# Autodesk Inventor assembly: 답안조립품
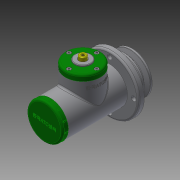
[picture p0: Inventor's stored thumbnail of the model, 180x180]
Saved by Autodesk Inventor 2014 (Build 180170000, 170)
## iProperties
Created: 2016-08
Part Number: 답안조립품
Document SubType Name: Assembly
Designer: USER
Author: USER
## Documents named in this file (25)
- C:\Users\USER\Desktop\460807V1008\답안조립품.iam
- C:\Users\USER\Desktop\460807V1008\본체.ipt
- C:\Users\USER\Desktop\460807V1008\V-벨트풀리.ipt
- C:\Users\USER\Desktop\460807V1008\너트 M10.ipt
- C:\Users\USER\Desktop\460807V1008\링크.ipt
- C:\Users\USER\Desktop\460807V1008\멈춤링 15 x 1.ipt
- C:\Users\USER\Desktop\460807V1008\멈춤링 35x1.6.ipt
- C:\Users\USER\Desktop\460807V1008\베어링 15 x 35 x 11.ipt
- C:\Users\USER\Desktop\460807V1008\볼트 M4 x 10.ipt
- C:\Users\USER\Desktop\460807V1008\볼트 M4 x 12.ipt
- C:\Users\USER\Desktop\460807V1008\부시1.ipt
- C:\Users\USER\Desktop\460807V1008\부시2.ipt
- C:\Users\USER\Desktop\460807V1008\분할핀 1.6 x 12.ipt
- C:\Users\USER\Desktop\460807V1008\사이드 커버.ipt
- 사이드 커버.ipt
- C:\Users\USER\Desktop\460807V1008\슬라이더.ipt
- C:\Users\USER\Desktop\460807V1008\오일 실 15 25 7.ipt
- C:\Users\USER\Desktop\460807V1008\와셔 4x16.ipt
- C:\Users\USER\Desktop\460807V1008\와셔 10x21.ipt
- C:\Users\USER\Desktop\460807V1008\클래스터 핀 6 x 24.ipt
- C:\Users\USER\Desktop\460807V1008\키 4 x 4 x 18.ipt
- C:\Users\USER\Desktop\460807V1008\탑 부시.ipt
- C:\Users\USER\Desktop\460807V1008\탑 커버.ipt
- 탑 커버.ipt
- C:\Users\USER\Desktop\460807V1008\편심축.ipt
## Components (6 placed, 3 different names)
1. V-벨트풀리:1
2. ISO 4017 M4 x 10:1
3. ISO 4762 M4 x 12:1
4. ISO 4762 M4 x 12:2
5. ISO 4762 M4 x 12:3
6. ISO 4762 M4 x 12:4
